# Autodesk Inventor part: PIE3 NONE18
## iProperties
Shininess: 64.0
Length Units: 11269
Angle Units: 11279
Time Units: 11290
Mass Units: 11286
Length Display Precision: 3
Angle Display Precision: 2
Compacted: True
Part Number: PIE3 NONE18
Document SubType Name: Modeling
Created: 2004-08
Designer: John Blackburn
Manufacturer: Standard
Standards Organization: Custom
Density: 0.0
Volumn: 0.0
Area: 0.0
PropertySet Name: Model Information
Control State: 0
Master: False
Checked Out: False
Author: John Blackburn
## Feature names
1. Erst1
